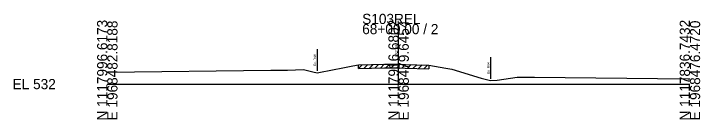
# Model space of a CAD drawing. Extents: x -26 to 163, y -10 to 24518.
# Drawn here: x -25.7 to 162.8, y 16490.3 to 16519.4 of the extents above; entities that cross this region are included whole.
import ezdxf

# ---------------------------------------------------------------- set-up
doc = ezdxf.new("R2010")
doc.units = 0
for name, color, linetype in [('RD_GPK_XS_Cell', 7, 'Continuous'), ('RD_XS_ExGround', 7, 'Continuous'), ('RD_XS_ExPaveRet', 7, 'Continuous'), ('RD_XS_ExRW', 7, 'Continuous'), ('RD_XS_TX_Elev_EX', 7, 'Continuous')]:
    doc.layers.add(name, color=color, linetype=linetype)

msp = doc.modelspace()

# ---------------------------------------------------------------- linework, layer by layer
at = {"layer": 'RD_GPK_XS_Cell'}
for p, q in [((80, 16500), (80, 16516.54)), ((0, 16500), (80, 16500)), ((80, 16500), (160, 16500))]:
    msp.add_line(p, q, dxfattribs=at)
at = {"layer": 'RD_XS_ExGround'}
msp.add_lwpolyline([(0, 16503.27), (44.87, 16503.84), (49.53, 16503.83), (53.88, 16503.99), (56.48, 16503.42), (57.59, 16503.13), (62.3, 16504.03), (64.18, 16504.41), (67.47, 16505.03), (68.99, 16505.29), (76.08, 16505.45), (78.94, 16505.51), (80, 16505.48), (81.79, 16505.42), (88.3, 16505.2), (92.96, 16504.38), (94.63, 16504.09), (102.66, 16501.66), (105.25, 16500.96), (107.06, 16501.11), (112.53, 16501.9), (117.34, 16501.89), (159.52, 16501.41), (160, 16501.41)], dxfattribs=at)
at = {"layer": 'RD_XS_ExPaveRet'}
for p, q in [((68.99, 16504.29), (70.02, 16505.31)), ((68.99, 16504.29), (68.99, 16505.29)), ((68.99, 16504.29), (76.08, 16504.45)), ((70.49, 16504.32), (71.52, 16505.35)), ((71.99, 16504.36), (73.02, 16505.38)), ((73.49, 16504.39), (74.52, 16505.42)), ((74.99, 16504.43), (76.02, 16505.45)), ((76.08, 16504.45), (78.94, 16504.51)), ((76.49, 16504.46), (77.51, 16505.48)), ((77.99, 16504.49), (79.01, 16505.51)), ((78.94, 16504.51), (80, 16504.48)), ((79.49, 16504.5), (80.46, 16505.46)), ((80, 16504.48), (81.79, 16504.42)), ((80.99, 16504.45), (81.96, 16505.41)), ((81.79, 16504.42), (88.3, 16504.2)), ((82.49, 16504.4), (83.46, 16505.36)), ((83.99, 16504.35), (84.96, 16505.31)), ((85.49, 16504.3), (86.46, 16505.26)), ((86.99, 16504.25), (87.96, 16505.22)), ((88.3, 16505.2), (88.3, 16504.2))]:
    msp.add_line(p, q, dxfattribs=at)
at = {"layer": 'RD_XS_ExRW'}
for p, q in [((57.59, 16509.63), (57.59, 16503.63)), ((105.25, 16507.46), (105.25, 16501.46))]:
    msp.add_line(p, q, dxfattribs=at)

# ---------------------------------------------------------------- texts
at = {"layer": 'RD_GPK_XS_Cell'}
for s, p in [('S103REL', (70, 16516.54)), ('68+00.00 / 2', (70, 16513.74)), ('EL 532', (-26, 16498.6))]:
    msp.add_text(s, height=2.8, dxfattribs=at).set_placement(p)
for s, p in [('N 1117996.6173', (0, 16490)), ('N 1117916.6802', (80, 16490)), ('E 1968479.6454', (82.8, 16490)), ('N 1117836.7432', (160, 16490)), ('E 1968482.8188', (2.8, 16490)), ('E 1968476.4720', (162.8, 16490))]:
    msp.add_text(s, height=2.8, rotation=90, dxfattribs=at).set_placement(p)
at = {"layer": 'RD_XS_ExRW'}
for p in [(57.34, 16504.97), (105, 16502.8)]:
    msp.add_text('Ex. R/W ', height=0.65, rotation=90, dxfattribs=at).set_placement(p)
at = {"layer": 'RD_XS_TX_Elev_EX'}
msp.add_text('537.48', height=0.8, rotation=90, dxfattribs=at).set_placement((79.9, 16507.48))

doc.saveas('drawing.dxf')
